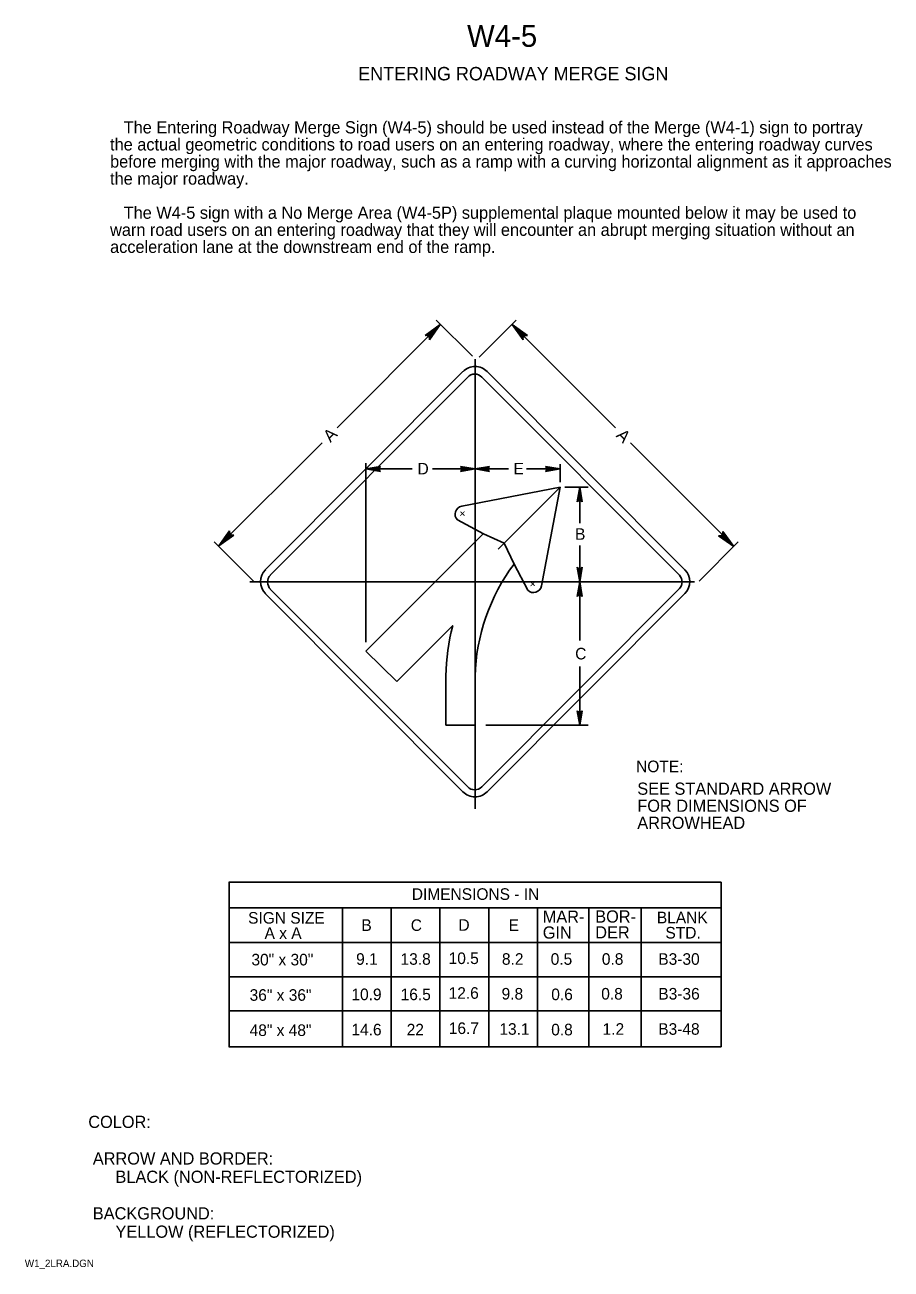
# Model space of a CAD drawing. Extents: x 0.013 to 0.19, y 0.004 to 0.259.
import ezdxf

# ---------------------------------------------------------------- set-up
doc = ezdxf.new("R2010")
doc.units = 0
for name, color, linetype in [('1', 7, 'Continuous'), ('2', 7, 'Continuous'), ('3', 7, 'Continuous')]:
    doc.layers.add(name, color=color, linetype=linetype)

# ---------------------------------------------------------------- blocks, each defined once
blk = doc.blocks.new('RARROW')
at = {"layer": '3'}
for p, q in [((-2.156, 0.28500000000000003), (-2.2665, 0.384625)), ((-2.2665, 0.384625), (0, 0)), ((0, 0), (-2.2665, -0.379125)), ((-2.156, 0.28500000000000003), (-2.075625, 0.12075)), ((0, 0), (-2.156, 0.28500000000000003)), ((-2.14975, -0.2705), (0, 0)), ((-2.075625, 0.12075), (0, 0)), ((0, 0), (-2.074, -0.108)), ((-2.2665, -0.379125), (-2.14975, -0.2705)), ((-2.074, -0.108), (-2.14975, -0.2705))]:
    blk.add_line(p, q, dxfattribs=at)

msp = doc.modelspace()

# ---------------------------------------------------------------- linework, layer by layer
at = {"layer": '3'}
for p, q in [((0.0764956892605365, 0.17642483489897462), (0.0976888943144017, 0.19761803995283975)), ((0.10424986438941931, 0.19105706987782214), (0.09680500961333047, 0.19850192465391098)), ((0.10556980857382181, 0.19087674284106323), (0.11319499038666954, 0.19850192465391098)), ((0.13350431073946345, 0.17642483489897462), (0.11231110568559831, 0.19761803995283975)), ((0.10475, 0.19045858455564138), (0.10475, 0.09827483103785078)), ((0.06175, 0.14730693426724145), (0.10225000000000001, 0.18793193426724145)), ((0.06275, 0.14618193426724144), (0.10325000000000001, 0.18680693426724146)), ((0.106125, 0.18680693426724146), (0.146625, 0.14618193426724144)), ((0.10725, 0.18793193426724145), (0.14775, 0.14730693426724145)), ((0.073402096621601, 0.1733312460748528), (0.05218889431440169, 0.15211803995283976)), ((0.136597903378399, 0.1733312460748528), (0.1578111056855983, 0.15211803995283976)), ((0.08240519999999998, 0.13248186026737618), (0.08240519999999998, 0.16918509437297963)), ((0.10475, 0.16354306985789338), (0.10475, 0.16918509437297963)), ((0.12218459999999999, 0.16524530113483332), (0.12218459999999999, 0.1689324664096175)), ((0.09188151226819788, 0.16797007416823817), (0.08239317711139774, 0.16797007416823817)), ((0.09603182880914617, 0.16797007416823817), (0.10474473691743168, 0.16797007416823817)), ((0.11163461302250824, 0.16797007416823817), (0.10474473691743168, 0.16797007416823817)), ((0.11530699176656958, 0.16797007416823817), (0.12216756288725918, 0.16797007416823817)), ((0.1221846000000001, 0.16423443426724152), (0.10203205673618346, 0.16034534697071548)), ((0.10945667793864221, 0.15150651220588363), (0.1221846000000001, 0.16423443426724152)), ((0.1221846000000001, 0.16423443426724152), (0.11838390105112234, 0.1439935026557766)), ((0.12313845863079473, 0.16423443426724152), (0.12795041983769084, 0.16423443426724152)), ((0.12619405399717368, 0.1642347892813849), (0.12619405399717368, 0.1568363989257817)), ((0.10114817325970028, 0.15751691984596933), (0.10645147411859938, 0.1546884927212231)), ((0.08240519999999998, 0.1306422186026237), (0.10636308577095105, 0.15460010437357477)), ((0.1106941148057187, 0.1527439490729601), (0.10645147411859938, 0.1546884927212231)), ((0.059348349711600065, 0.1449585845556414), (0.05130500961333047, 0.153001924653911)), ((0.1106941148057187, 0.1527439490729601), (0.11274618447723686, 0.14846880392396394)), ((0.12619405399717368, 0.15227706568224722), (0.12619405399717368, 0.1448064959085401)), ((0.15065165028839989, 0.1449585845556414), (0.15869499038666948, 0.153001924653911)), ((0.11555547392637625, 0.14310961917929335), (0.11274233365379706, 0.14846366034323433)), ((0.058625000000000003, 0.14480693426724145), (0.14975, 0.14480693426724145)), ((0.10325000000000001, 0.10280693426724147), (0.06275, 0.14330693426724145)), ((0.146625, 0.14343193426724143), (0.106125, 0.10280693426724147)), ((0.1221846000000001, 0.1448069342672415), (0.12795041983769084, 0.1448069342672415)), ((0.12619405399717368, 0.1448064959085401), (0.12619405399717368, 0.13282471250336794)), ((0.10225000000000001, 0.10180693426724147), (0.06175, 0.14243193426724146)), ((0.14775, 0.14243193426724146), (0.10725, 0.10180693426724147)), ((0.0886903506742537, 0.12437622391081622), (0.10018117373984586, 0.13586704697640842)), ((0.08240519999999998, 0.1306422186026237), (0.0886903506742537, 0.12437622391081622)), ((0.09875, 0.11541693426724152), (0.09875, 0.1255900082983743)), ((0.10475, 0.11541693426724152), (0.10475, 0.12551017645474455)), ((0.12619405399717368, 0.12744734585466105), (0.12619405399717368, 0.11541744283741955)), ((0.09875, 0.11541693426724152), (0.10475, 0.11541693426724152)), ((0.10697026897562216, 0.11541693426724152), (0.12795041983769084, 0.11541693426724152)), ((0.05431185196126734, 0.08326151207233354), (0.15518814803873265, 0.08326151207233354)), ((0.05435343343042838, 0.08325864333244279), (0.05435343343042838, 0.04951151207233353)), ((0.15518814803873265, 0.08326151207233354), (0.15518814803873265, 0.04951151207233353)), ((0.15518814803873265, 0.07801151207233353), (0.05431185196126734, 0.07801151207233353)), ((0.07756814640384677, 0.07800864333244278), (0.07756814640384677, 0.04951151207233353)), ((0.08756814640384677, 0.07800864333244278), (0.08756814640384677, 0.04951151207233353)), ((0.09756814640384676, 0.07800864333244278), (0.09756814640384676, 0.04951151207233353)), ((0.10756814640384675, 0.07800864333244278), (0.10756814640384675, 0.04951151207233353)), ((0.11756814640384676, 0.07800864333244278), (0.11756814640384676, 0.04951151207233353)), ((0.12804314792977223, 0.07800864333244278), (0.12804314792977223, 0.04951151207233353)), ((0.1387931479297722, 0.07800864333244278), (0.1387931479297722, 0.04951151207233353)), ((0.05431185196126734, 0.07088651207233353), (0.15518814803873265, 0.07088651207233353)), ((0.05431185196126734, 0.06388651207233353), (0.15518814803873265, 0.06388651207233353)), ((0.05431185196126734, 0.056886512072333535), (0.15518814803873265, 0.056886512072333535)), ((0.05431185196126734, 0.04951151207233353), (0.15518814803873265, 0.04951151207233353))]:
    msp.add_line(p, q, dxfattribs=at)
for centre, radius, start, end in [((0.10477220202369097, 0.1854911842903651), 0.0034780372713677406, 44.56843888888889, 135.49785833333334), ((0.1046875, 0.18539256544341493), 0.0020166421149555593, 44.535291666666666, 135.46471111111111), ((0.10233782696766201, 0.1586974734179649), 0.0016760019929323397, 100.51193055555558, 224.78002222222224), ((0.14488517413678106, 0.12440342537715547), 0.04015043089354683, 143.1744700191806, 178.42043540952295), ((0.06426195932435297, 0.14486656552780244), 0.003470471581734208, 135.38381666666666, 224.61618055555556), ((0.06433263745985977, 0.14476799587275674), 0.0020894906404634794, 135.70475555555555, 224.93711944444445), ((0.145225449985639, 0.1448069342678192), 0.0019619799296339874, 315.5069555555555, 44.49304166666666), ((0.1452689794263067, 0.14486943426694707), 0.0034780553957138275, 315.50695833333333, 44.49304444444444), ((0.11673602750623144, 0.14429927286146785), 0.0016760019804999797, 225.21997777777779, 349.4880694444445), ((0.14488517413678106, 0.12440342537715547), 0.046150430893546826, 165.61733378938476, 178.52669444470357), ((0.1046875, 0.10418211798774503), 0.0019893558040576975, 223.73079444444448, 316.2692083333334), ((0.1047499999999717, 0.10419855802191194), 0.003459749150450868, 223.73079444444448, 316.2692083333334)]:
    msp.add_arc(centre, radius, start, end, dxfattribs=at)

# ---------------------------------------------------------------- block references
for p, xscale, yscale, rotation in [((0.097625, 0.19755693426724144), 0.0016545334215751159, 0.0016366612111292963, 44.999999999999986), ((0.112375, 0.19755693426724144), 0.0016545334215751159, 0.0016366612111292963, 135.00000000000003), ((0.08239317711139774, 0.16797007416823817), 0.0013236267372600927, -0.001309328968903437, 180), ((0.10474473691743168, 0.16797007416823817), 0.0013236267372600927, -0.001309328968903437, 180), ((0.12619405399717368, 0.1642347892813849), 0.0013236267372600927, -0.001309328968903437, 90), ((0.05225, 0.15218193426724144), 0.001654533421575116, 0.001636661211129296, -135), ((0.15775, 0.15205693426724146), 0.0016545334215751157, 0.001636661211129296, -45), ((0.12619405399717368, 0.1448064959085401), 0.0013236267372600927, -0.001309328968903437, -90.00000000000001), ((0.12619405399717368, 0.1448064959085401), 0.0013236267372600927, -0.001309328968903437, 90), ((0.12619405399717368, 0.11541744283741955), 0.0013236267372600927, -0.001309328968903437, -90.00000000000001)]:
    msp.add_blockref('RARROW', p, dxfattribs=dict(at, xscale=xscale, yscale=yscale, rotation=rotation))
at = {"layer": '3', "xscale": 0.0013236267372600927, "yscale": -0.001309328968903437}
for p in [(0.10474473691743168, 0.16797007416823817), (0.12216756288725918, 0.16797007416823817)]:
    msp.add_blockref('RARROW', p, dxfattribs=at)

# ---------------------------------------------------------------- texts
at = {"layer": '1'}
for s, height, p in [('W4-5', 0.0045000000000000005, (0.1031075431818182, 0.2545)), ('ENTERING ROADWAY MERGE SIGN', 0.00275025, (0.08081244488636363, 0.247625)), ('NOTE:', 0.0023752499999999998, (0.13775, 0.10580693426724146)), ('SEE STANDARD ARROW', 0.0024997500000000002, (0.138, 0.10118193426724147)), ('FOR DIMENSIONS OF', 0.0024997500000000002, (0.138, 0.09768193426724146)), ('ARROWHEAD', 0.0024997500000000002, (0.138, 0.09418193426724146)), ('COLOR:', 0.0024997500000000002, (0.025500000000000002, 0.032875)), (' ARROW AND BORDER:', 0.0024997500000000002, (0.025500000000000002, 0.025375)), ('      BLACK (NON-REFLECTORIZED)', 0.0024997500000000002, (0.025500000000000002, 0.021625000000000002)), (' BACKGROUND:', 0.0024997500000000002, (0.025500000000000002, 0.014125)), ('      YELLOW (REFLECTORIZED)', 0.0024997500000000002, (0.025500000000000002, 0.010375)), ('W1_2LRA.DGN', 0.0015, (0.0125, 0.004375))]:
    msp.add_text(s, height=height, dxfattribs=at).set_placement(p)
at = {"layer": '2'}
for s, p in [('   The Entering Roadway Merge Sign (W4-5) should be used instead of the Merge (W4-1) sign to portray', (0.029965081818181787, 0.23675025)), ('the actual geometric conditions to road users on an entering roadway, where the entering roadway curves ', (0.029965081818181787, 0.2332505)), ('before merging with the major roadway, such as a ramp with a curving horizontal alignment as it approaches ', (0.029965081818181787, 0.22975075)), ('the major roadway.  ', (0.029965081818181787, 0.226251)), ('   The W4-5 sign with a No Merge Area (W4-5P) supplemental plaque mounted below it may be used to', (0.029965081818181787, 0.2192515)), ('warn road users on an entering roadway that they will encounter an abrupt merging situation without an', (0.029965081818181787, 0.21575175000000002)), ('acceleration lane at the downstream end of the ramp.', (0.029965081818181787, 0.21225200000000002))]:
    msp.add_text(s, height=0.0024997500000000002, dxfattribs=at).set_placement(p)
at = {"layer": '3'}
for s, height, rotation, p in [('A', 0.0024997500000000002, 45, (0.075125, 0.17330693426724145)), ('A', 0.0024997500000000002, 315, (0.1335, 0.17468193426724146)), ('+', 0.00177825, 135, (0.10326949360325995, 0.15893113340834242)), ('+', 0.00177825, 135, (0.11767679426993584, 0.14452383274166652))]:
    msp.add_text(s, height=height, rotation=rotation, dxfattribs=at).set_placement(p)
for s, height, p in [('D', 0.0023752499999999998, (0.09295947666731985, 0.16684507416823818)), ('E', 0.0023752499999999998, (0.11262660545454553, 0.16684507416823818)), ('B', 0.0023752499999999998, (0.12524812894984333, 0.1534437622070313)), ('C', 0.0023752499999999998, (0.12527116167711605, 0.12892430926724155)), ('DIMENSIONS - IN', 0.0023752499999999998, (0.09179229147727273, 0.07963651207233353)), ('SIGN SIZE', 0.0023752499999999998, (0.058244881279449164, 0.07476151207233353)), ('MAR-', 0.0024997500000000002, (0.11862656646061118, 0.07493725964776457)), ('BOR-', 0.0024997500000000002, (0.1293765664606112, 0.07497805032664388)), ('BLANK', 0.0023752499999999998, (0.14200945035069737, 0.07483743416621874)), ('A x A', 0.0023752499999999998, (0.06161988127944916, 0.07163651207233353)), ('B', 0.0023752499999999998, (0.08146824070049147, 0.07327015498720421)), ('C', 0.0023752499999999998, (0.09157761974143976, 0.07326282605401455)), ('D', 0.0023752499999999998, (0.10134283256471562, 0.0732942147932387)), ('E', 0.0023752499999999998, (0.11162325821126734, 0.07326151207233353)), ('GIN', 0.0024997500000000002, (0.11862656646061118, 0.07168725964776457)), ('DER', 0.0024997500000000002, (0.1293765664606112, 0.07172805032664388)), ('STD.', 0.0023752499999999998, (0.14375945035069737, 0.07171243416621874)), ('10.5', 0.0023752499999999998, (0.09933718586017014, 0.06648027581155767)), ('30" x 30"', 0.0023752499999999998, (0.058932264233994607, 0.06619888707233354)), ('9.1', 0.0023752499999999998, (0.08038138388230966, 0.06632388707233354)), ('13.8', 0.0023752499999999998, (0.089488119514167, 0.06632388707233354)), ('8.2', 0.0023752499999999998, (0.11025892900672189, 0.06632388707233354)), ('0.5', 0.0023752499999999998, (0.12024795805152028, 0.06632388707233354)), ('0.8', 0.0023752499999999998, (0.13073212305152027, 0.06632388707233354)), ('B3-30', 0.0023752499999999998, (0.14230311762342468, 0.06632388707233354)), ('36" x 36"', 0.0023752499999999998, (0.05855726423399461, 0.05894888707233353)), ('10.9', 0.0023752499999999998, (0.07941832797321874, 0.059073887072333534)), ('16.5', 0.0023752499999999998, (0.08950395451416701, 0.059073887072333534)), ('12.6', 0.0023752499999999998, (0.09933430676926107, 0.059355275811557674)), ('9.8', 0.0023752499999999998, (0.11019450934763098, 0.059198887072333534)), ('0.6', 0.0023752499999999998, (0.12037007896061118, 0.059073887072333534)), ('0.8', 0.0023752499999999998, (0.13060712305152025, 0.059198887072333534)), ('B3-36', 0.0023752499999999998, (0.14230815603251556, 0.059198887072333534)), ('48" x 48"', 0.0023752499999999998, (0.05855726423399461, 0.05172907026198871)), ('14.6', 0.0023752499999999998, (0.07941472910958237, 0.05185407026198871)), ('22', 0.0023752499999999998, (0.09074016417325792, 0.05185407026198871)), ('16.7', 0.0023752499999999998, (0.09936993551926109, 0.05213545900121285)), ('13.1', 0.0023752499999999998, (0.10973457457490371, 0.05197907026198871)), ('0.8', 0.0023752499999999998, (0.12035712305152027, 0.05185407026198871)), ('1.2', 0.0023752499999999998, (0.13088747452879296, 0.05197907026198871)), ('B3-48', 0.0023752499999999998, (0.14229520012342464, 0.05197907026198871))]:
    msp.add_text(s, height=height, dxfattribs=at).set_placement(p)

doc.saveas('drawing.dxf')
